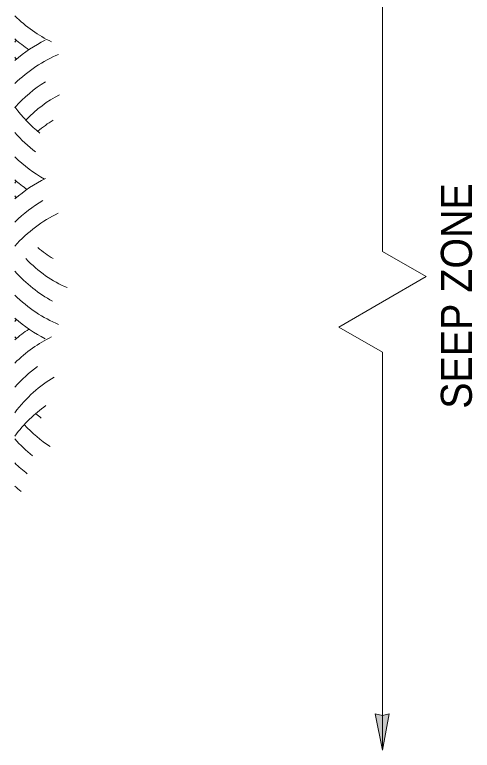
# Model space of a CAD drawing. Extents: x 17672 to 18472, y -9785 to -9267.
# Drawn here: x 17868.8 to 17920.9, y -9423.5 to -9339.8 of the extents above; entities that cross this region are included whole.
import ezdxf

# ---------------------------------------------------------------- set-up
doc = ezdxf.new("R2010")
doc.units = 0
doc.header["$LTSCALE"] = 1.4
for name, color, linetype, lineweight in [('1', 7, 'Continuous', 13), ('15', 7, 'Continuous', 13), ('16', 7, 'Continuous', 13), ('20', 7, 'Continuous', 25)]:
    doc.layers.add(name, color=color, linetype=linetype, lineweight=lineweight)

msp = doc.modelspace()

# ---------------------------------------------------------------- hatches: boundary and pattern name
at = {"layer": '16'}
msp.add_hatch(color=256, dxfattribs=at).paths.add_polyline_path([(17910.629, -9423.519), (17911.411, -9419.381), (17910.629, -9419.567), (17909.808, -9419.381)])

# ---------------------------------------------------------------- linework, layer by layer
at = {"layer": '1'}
for centre, major_axis, start_param, end_param in [((17878.785, -9319.833), (0, -24.471), 5.678359, 5.946281), ((17878.785, -9319.833), (0, -26.675), 5.734425, 5.830081), ((17878.785, -9367.81), (0, 26.675), 0.347284, 0.54876), ((17855.034, -9321.851), (0, -28.469), 0.735703, 0.74718), ((17878.785, -9367.81), (0, 24.471), 0.28844, 0.604826), ((17855.034, -9365.791), (0, 28.469), 5.536005, 5.547483), ((17878.785, -9367.81), (0, 22.266), 0.419017, 0.675019), ((17878.785, -9367.81), (0, 20.062), 0.347048, 0.649981), ((17878.785, -9335.867), (0, -20.062), 5.517669, 5.766375), ((17878.855, -9370.274), (0, 20.062), 0.405446, 0.543163), ((17878.785, -9335.867), (0, -22.266), 5.608166, 5.786033), ((17878.785, -9335.867), (0, -24.471), 5.678359, 5.89692), ((17878.785, -9383.557), (0, 26.675), 0.346641, 0.54876), ((17878.785, -9335.867), (0, -26.675), 5.734425, 5.819072), ((17855.034, -9337.886), (0, -28.469), 0.735703, 0.74718), ((17878.785, -9383.557), (0, 24.471), 0.396562, 0.604826), ((17855.034, -9381.539), (0, 28.469), 5.536005, 5.547483), ((17878.785, -9383.557), (0, 22.266), 0.321019, 0.675019), ((17878.855, -9349.15), (0, -20.062), 5.740022, 5.87774), ((17878.785, -9351.615), (0, -20.062), 5.633205, 5.999911), ((17878.785, -9351.615), (0, -22.266), 5.608166, 5.918958), ((17878.785, -9351.615), (0, -24.471), 5.678359, 5.994746), ((17878.785, -9351.615), (0, -26.675), 5.734425, 5.935901), ((17855.034, -9353.633), (0, -28.469), 0.735703, 0.74718), ((17878.785, -9399.592), (0, 26.675), 0.453104, 0.54876), ((17878.785, -9399.592), (0, 24.471), 0.336904, 0.604826), ((17855.034, -9397.574), (0, 28.469), 5.536005, 5.547483), ((17878.785, -9399.592), (0, 22.266), 0.481461, 0.675019), ((17878.785, -9399.592), (0, 20.062), 0.393014, 0.765516), ((17878.785, -9402.243), (0, 20.062), 0.464937, 0.765516), ((17878.855, -9368.237), (0, -20.062), 5.720851, 5.771052), ((17878.785, -9370.702), (0, -20.062), 5.616853, 5.85583), ((17878.785, -9370.702), (0, -22.266), 5.608166, 5.761688), ((17878.785, -9370.702), (0, -24.471), 5.678359, 5.774233), ((17878.785, -9370.702), (0, -26.675), 5.734425, 5.779681)]:
    msp.add_ellipse(centre, major_axis=major_axis, ratio=0.719298, start_param=start_param, end_param=end_param, dxfattribs=at)
at = {"layer": '15'}
for p, q in [((17910.629, -9321.456), (17910.629, -9366.771)), ((17910.629, -9378.234), (17910.629, -9423.519))]:
    msp.add_line(p, q, dxfattribs=at)
msp.add_lwpolyline([(17910.629, -9378.234), (17905.658, -9375.376), (17915.6, -9369.628), (17910.629, -9366.771)], dxfattribs=at)
at = {"layer": '16'}
msp.add_lwpolyline([(17910.629, -9423.519), (17911.411, -9419.381), (17910.629, -9419.567), (17909.808, -9419.381)], close=True, dxfattribs=at)

# ---------------------------------------------------------------- texts
at = {"layer": '20', "width": 0.95}
msp.add_text('SEEP ZONE', height=3.529, rotation=90, dxfattribs=at).set_placement((17920.813, -9384.668))

doc.saveas('drawing.dxf')
